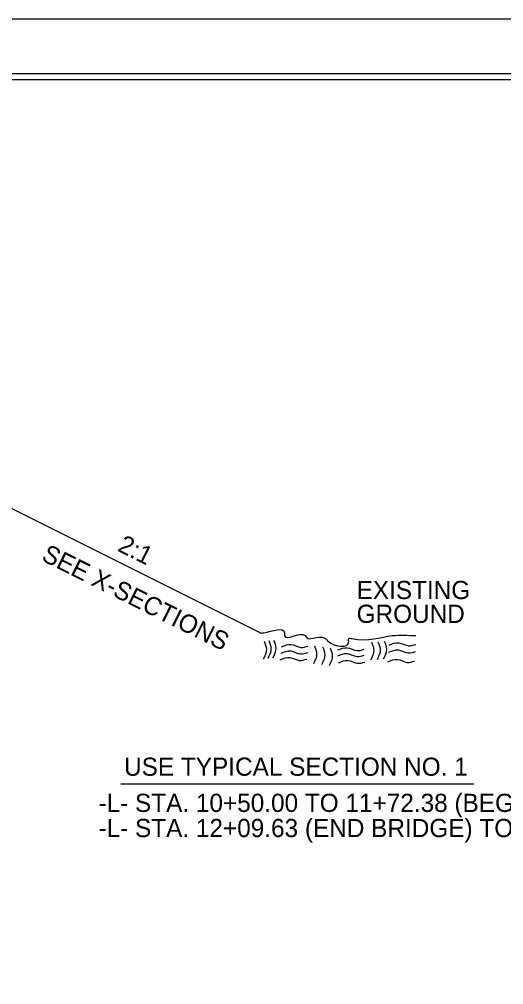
# Model space of a CAD drawing. Extents: x 575722 to 576066, y -53107 to -52774.
# Drawn here: x 575922.9 to 575942.85, y -52838.56 to -52798.76 of the extents above; entities that cross this region are included whole.
import ezdxf

# ---------------------------------------------------------------- set-up
doc = ezdxf.new("R2010")
doc.units = 0
for name, color, linetype in [('Old_Level_2', 7, 'Continuous'), ('Prop DSN Text', 7, 'Continuous'), ('Sheet Cutting Line CELL', 7, 'Continuous'), ('Sheet Plot Border Inside CELL', 7, 'Continuous'), ('Sheet Plot Border Outside CELL', 7, 'Continuous'), ('Sheet Typical CELL', 7, 'Continuous'), ('Typical Slope Point Local CELL', 7, 'Continuous'), ('Typical Text Grade Point CELL', 7, 'Continuous')]:
    doc.layers.add(name, color=color, linetype=linetype)

msp = doc.modelspace()

# ---------------------------------------------------------------- linework, layer by layer
at = {"layer": 'Old_Level_2'}
for points in [[(575932.845, -52824.064), (575932.987, -52824.048), (575933.827, -52824.048), (575933.827, -52824.168), (575934.667, -52824.168), (575934.787, -52824.288), (575934.907, -52824.288), (575935.507, -52824.288), (575935.627, -52824.408), (575936.467, -52824.408), (575936.467, -52824.288), (575936.587, -52824.288), (575938.267, -52824.168), (575939.224, -52824.168)], [(575932.981, -52824.401), (575933.075, -52824.724), (575932.94, -52825.141)], [(575933.169, -52824.374), (575933.263, -52824.697), (575933.129, -52825.114)], [(575933.37, -52824.361), (575933.465, -52824.684), (575933.33, -52825.1)], [(575933.7, -52824.623), (575934.09, -52824.529), (575934.493, -52824.65), (575934.788, -52824.596)], [(575935.051, -52824.59), (575935.145, -52824.912), (575935.01, -52825.329)], [(575935.387, -52824.63), (575935.481, -52824.952), (575935.346, -52825.369)], [(575935.696, -52824.67), (575935.79, -52824.993), (575935.655, -52825.409)], [(575936.012, -52824.758), (575936.401, -52824.664), (575936.805, -52824.785), (575937.1, -52824.731)], [(575937.403, -52824.442), (575937.497, -52824.764), (575937.362, -52825.181)], [(575937.671, -52824.428), (575937.765, -52824.751), (575937.631, -52825.168)], [(575937.927, -52824.401), (575938.021, -52824.724), (575937.886, -52825.141)], [(575938.135, -52824.556), (575938.525, -52824.462), (575938.928, -52824.583), (575939.224, -52824.529)], [(575933.646, -52825.161), (575934.036, -52825.067), (575934.439, -52825.188), (575934.735, -52825.134)], [(575933.686, -52824.892), (575934.076, -52824.798), (575934.479, -52824.919), (575934.775, -52824.865)], [(575936.012, -52825), (575936.401, -52824.905), (575936.805, -52825.026), (575937.1, -52824.973)], [(575938.122, -52824.852), (575938.512, -52824.758), (575938.915, -52824.879), (575939.21, -52824.825)], [(575936.039, -52825.282), (575936.428, -52825.188), (575936.831, -52825.309), (575937.127, -52825.255)], [(575938.082, -52825.241), (575938.471, -52825.147), (575938.874, -52825.268), (575939.17, -52825.215)]]:
    msp.add_spline(points, degree=3, dxfattribs=at)
at = {"layer": 'Prop DSN Text'}
msp.add_line((575927.081, -52830.273), (575941.613, -52830.273), dxfattribs=at)
at = {"layer": 'Sheet Cutting Line CELL'}
msp.add_line((575964.975, -52798.762), (575796.575, -52798.762), dxfattribs=at)
at = {"layer": 'Sheet Plot Border Inside CELL'}
msp.add_lwpolyline([(575964.525, -52801.007), (575797.875, -52801.007), (575797.875, -52906.517), (575964.525, -52906.517)], close=True, dxfattribs=at)
at = {"layer": 'Sheet Plot Border Outside CELL'}
msp.add_lwpolyline([(575964.975, -52798.762), (575796.575, -52798.762), (575796.575, -52908.762), (575964.975, -52908.762)], close=True, dxfattribs=at)
at = {"layer": 'Sheet Typical CELL'}
msp.add_lwpolyline([(575963.275, -52801.262), (575813.275, -52801.262), (575813.275, -52906.262), (575963.275, -52906.262)], close=True, dxfattribs=at)
at = {"layer": 'Typical Slope Point Local CELL'}
msp.add_line((575932.845, -52824.064), (575921.682, -52818.482), dxfattribs=at)

# ---------------------------------------------------------------- texts
at = {"layer": 'Prop DSN Text'}
for s, p in [('USE TYPICAL SECTION NO. 1', (575927.212, -52829.944)), ('-L- STA. 10+50.00 TO 11+72.38 (BEGIN BRIDGE)', (575926.158, -52831.435)), ('-L- STA. 12+09.63 (END BRIDGE) TO 12+55.13', (575926.158, -52832.472))]:
    msp.add_text(s, height=0.75, dxfattribs=at).set_placement(p)
at = {"layer": 'Typical Slope Point Local CELL'}
for s, p in [('2:1', (575926.9, -52820.656)), ('SEE X-SECTIONS', (575923.763, -52821.045))]:
    msp.add_text(s, height=0.75, rotation=333.434, dxfattribs=at).set_placement(p)
at = {"layer": 'Typical Text Grade Point CELL'}
for s, p in [('EXISTING', (575936.79, -52822.66)), ('GROUND', (575936.79, -52823.643))]:
    msp.add_text(s, height=0.75, dxfattribs=at).set_placement(p)

doc.saveas('drawing.dxf')
